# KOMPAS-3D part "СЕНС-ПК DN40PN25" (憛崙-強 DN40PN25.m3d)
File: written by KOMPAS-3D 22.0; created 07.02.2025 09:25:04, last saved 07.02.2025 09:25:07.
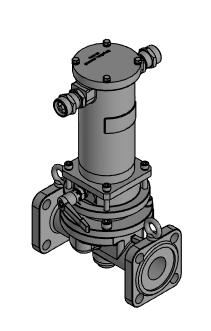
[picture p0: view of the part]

Document properties: Автор: setup; Полное имя файла: \\10.10.77.77\!! users\Савин А.Г\!Клапаны 3D для заказчика\СЕНС-ПК\1. СЕНС-ПК\СЕНС-ПК DN40PN25.m3d

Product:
- Body: Тело 3
    Масса: 16.691352
- Part/product: СЕНС-ПК DN40PN25
    Масса: 16.470884

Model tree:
1. Операция без истории:1

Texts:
  Body Specification ( left align )
  Body Specificaton ( centered )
